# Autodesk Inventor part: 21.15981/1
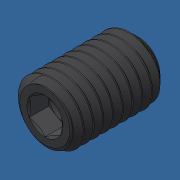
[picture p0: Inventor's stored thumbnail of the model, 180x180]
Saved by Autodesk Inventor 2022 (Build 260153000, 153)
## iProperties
Created: 2015-06
Material: Stainless Steel
Document SubType Name: Modeling
Designer: Admin
Density: 8 g/cm^3
Mass: 3.5153 g
Surface Area: 5.55071 cm^2
Volume: 0.439412 cm^3
Description: M8X12 SET SCREW FLAT POINT SS
Part Number: 21.15981/1
Vendor: S
Appearance: Gray
Stock Number: 21.15981/1 M8X12 SET SCREW FLAT POINT SS
Translation Standard: STEP AP203
FileName: 93245A142.step
PreProcessor: SolidWorks 2010
PostProcessor: Build: 160, Release: 2012 RTM - Date: Tue 03/01/2011
Sent Units: inch
Uncertainty: 1e-05
Author: Admin
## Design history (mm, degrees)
node "93245A1421"
node "Cut-Extrude12"
node "Base1"
